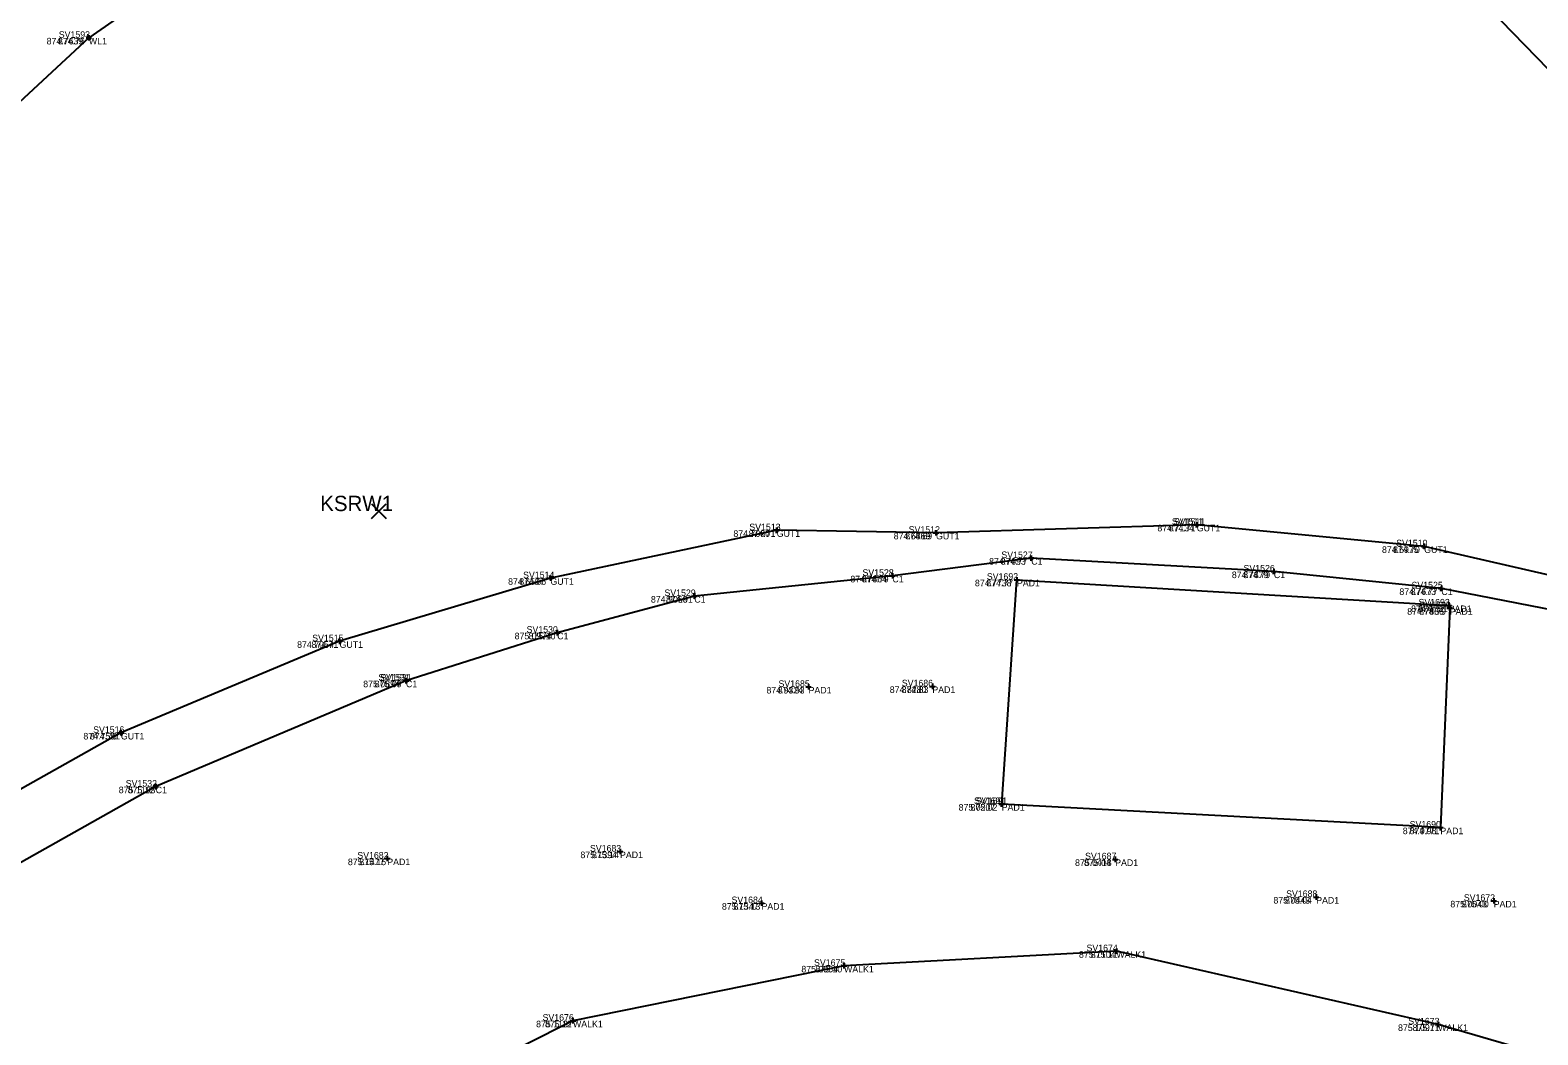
# Model space of a CAD drawing. Extents: x 1475924 to 1484301, y 375879 to 383357.
# Drawn here: x 1480162.05 to 1480175.83, y 379382.77 to 379391.95 of the extents above; entities that cross this region are included whole.
import ezdxf

# ---------------------------------------------------------------- set-up
doc = ezdxf.new("R2010")
doc.units = 0
for name, color, linetype in [('GK_Visualization', 7, 'Continuous'), ('PV_X_Curb', 7, 'Continuous'), ('PV_X_Walk', 7, 'Continuous'), ('RD_X_Concrete_Pad', 7, 'Continuous'), ('SV_X_Random_Point', 7, 'Continuous'), ('SV_X_Shot_Marker', 7, 'Continuous'), ('SV_X_Text_Comment', 7, 'Continuous'), ('SV_X_Text_Elevation', 7, 'Continuous'), ('SV_X_Text_Name', 7, 'Continuous'), ('UT_X_Water', 7, 'Continuous')]:
    doc.layers.add(name, color=color, linetype=linetype)

# ---------------------------------------------------------------- blocks, each defined once
blk = doc.blocks.new('X')
at = {"layer": 'SV_X_Random_Point'}
for p, q in [((-0.067, -0.067), (0.067, 0.067)), ((-0.067, 0.067), (0.067, -0.067))]:
    blk.add_line(p, q, dxfattribs=at)
blk = doc.blocks.new('GTM')
at = {"layer": 'SV_X_Shot_Marker'}
for p, q in [((-0.075, 0), (0.075, 0)), ((0, 0.075), (0, -0.075)), ((0, 0), (0, 0))]:
    blk.add_line(p, q, dxfattribs=at)

msp = doc.modelspace()

# ---------------------------------------------------------------- linework, layer by layer
at = {"layer": 'PV_X_Curb'}
for points in [[(1480233.83, 379339.39), (1480215.875, 379356.288), (1480200.731, 379370.664), (1480190.903, 379379.712), (1480187.53, 379382.642), (1480185.615, 379384.173), (1480181.928, 379385.583), (1480179.411, 379386.173), (1480174.793, 379387.235), (1480172.715, 379387.432), (1480170.332, 379387.359), (1480168.876, 379387.382), (1480166.808, 379386.944), (1480164.881, 379386.368), (1480162.883, 379385.531), (1480159.898, 379383.853), (1480158.052, 379382.754), (1480156.183, 379381.403), (1480155.05, 379380.342)], [(1480233.297, 379339.4), (1480215.447, 379356.074), (1480200.436, 379370.31), (1480191.889, 379378.223), (1480190.185, 379379.842), (1480188.303, 379381.604), (1480185.259, 379383.605), (1480181.861, 379385.001), (1480179.101, 379385.902), (1480178.705, 379386.045), (1480178.118, 379386.223), (1480177.29, 379386.43), (1480176.688, 379386.511), (1480174.95, 379386.851), (1480173.419, 379387.005), (1480171.202, 379387.128), (1480169.933, 379386.966), (1480168.123, 379386.781), (1480166.87, 379386.446), (1480165.488, 379386.008), (1480163.201, 379385.04), (1480160.165, 379383.332), (1480157.23, 379381.331), (1480156.058, 379380.439)]]:
    msp.add_lwpolyline(points, dxfattribs=at)
at = {"layer": 'PV_X_Walk'}
msp.add_lwpolyline([(1480327.959, 379242.083), (1480313.163, 379256.356), (1480297.576, 379270.674), (1480283.951, 379284.205), (1480267.344, 379299.69), (1480258.509, 379307.782), (1480244.036, 379321.372), (1480229.243, 379335.021), (1480213.414, 379349.982), (1480196.806, 379366.202), (1480192.296, 379370.271), (1480186.385, 379375.802), (1480181.8, 379379.27), (1480179.258, 379381.212), (1480177.445, 379382.131), (1480174.921, 379382.868), (1480171.98, 379383.537), (1480169.491, 379383.403), (1480167.014, 379382.902), (1480162.891, 379380.83), (1480161.298, 379379.691), (1480158.915, 379377.808)], dxfattribs=at)
at = {"layer": 'RD_X_Concrete_Pad'}
msp.add_lwpolyline([(1480175.026, 379386.67), (1480174.941, 379384.666), (1480170.932, 379384.881), (1480171.071, 379386.93), (1480175.017, 379386.695)], dxfattribs=at)
at = {"layer": 'SV_X_Shot_Marker'}
for p, q in [((1480162.611, 379391.894), (1480162.569, 379391.866)), ((1480162.604, 379391.859), (1480162.576, 379391.901)), ((1480162.59, 379391.88), (1480162.59, 379391.88)), ((1480168.9, 379387.382), (1480168.851, 379387.382)), ((1480168.875, 379387.357), (1480168.876, 379387.407)), ((1480168.876, 379387.382), (1480168.876, 379387.382)), ((1480170.357, 379387.359), (1480170.307, 379387.358)), ((1480170.332, 379387.334), (1480170.331, 379387.384)), ((1480170.332, 379387.359), (1480170.332, 379387.359)), ((1480172.74, 379387.43), (1480172.69, 379387.434)), ((1480172.713, 379387.407), (1480172.718, 379387.457)), ((1480172.715, 379387.432), (1480172.715, 379387.432)), ((1480174.817, 379387.229), (1480174.768, 379387.241)), ((1480174.787, 379387.211), (1480174.798, 379387.259)), ((1480174.793, 379387.235), (1480174.793, 379387.235)), ((1480171.227, 379387.127), (1480171.177, 379387.13)), ((1480171.201, 379387.103), (1480171.203, 379387.153)), ((1480171.202, 379387.128), (1480171.202, 379387.128)), ((1480166.832, 379386.95), (1480166.783, 379386.939)), ((1480166.813, 379386.92), (1480166.803, 379386.969)), ((1480166.808, 379386.944), (1480166.808, 379386.944)), ((1480169.958, 379386.969), (1480169.908, 379386.963)), ((1480169.936, 379386.941), (1480169.93, 379386.991)), ((1480169.933, 379386.966), (1480169.933, 379386.966)), ((1480171.046, 379386.932), (1480171.096, 379386.928)), ((1480171.069, 379386.905), (1480171.073, 379386.955)), ((1480171.071, 379386.93), (1480171.071, 379386.93)), ((1480173.443, 379387.002), (1480173.394, 379387.007)), ((1480173.416, 379386.98), (1480173.421, 379387.03)), ((1480173.419, 379387.005), (1480173.419, 379387.005)), ((1480168.148, 379386.783), (1480168.098, 379386.778)), ((1480168.126, 379386.756), (1480168.121, 379386.805)), ((1480174.974, 379386.846), (1480174.925, 379386.856)), ((1480174.945, 379386.826), (1480174.955, 379386.876)), ((1480174.95, 379386.851), (1480174.95, 379386.851)), ((1480168.123, 379386.781), (1480168.123, 379386.781)), ((1480174.992, 379386.697), (1480175.042, 379386.694)), ((1480175.051, 379386.669), (1480175.001, 379386.671)), ((1480175.018, 379386.72), (1480175.016, 379386.67)), ((1480175.017, 379386.695), (1480175.017, 379386.695)), ((1480175.027, 379386.695), (1480175.025, 379386.645)), ((1480175.026, 379386.67), (1480175.026, 379386.67)), ((1480164.905, 379386.376), (1480164.857, 379386.361)), ((1480164.889, 379386.344), (1480164.874, 379386.392)), ((1480164.881, 379386.368), (1480164.881, 379386.368)), ((1480166.894, 379386.452), (1480166.846, 379386.439)), ((1480166.877, 379386.421), (1480166.864, 379386.47)), ((1480166.87, 379386.446), (1480166.87, 379386.446)), ((1480165.512, 379386.016), (1480165.464, 379386.001)), ((1480165.495, 379385.984), (1480165.48, 379386.032)), ((1480165.488, 379386.008), (1480165.488, 379386.008)), ((1480169.167, 379385.976), (1480169.167, 379385.926)), ((1480170.273, 379385.956), (1480170.323, 379385.956)), ((1480170.298, 379385.981), (1480170.298, 379385.931)), ((1480170.298, 379385.956), (1480170.298, 379385.956)), ((1480169.142, 379385.951), (1480169.192, 379385.951)), ((1480169.167, 379385.951), (1480169.167, 379385.951)), ((1480162.906, 379385.541), (1480162.86, 379385.522)), ((1480162.893, 379385.508), (1480162.874, 379385.554)), ((1480162.883, 379385.531), (1480162.883, 379385.531)), ((1480163.224, 379385.049), (1480163.178, 379385.03)), ((1480163.211, 379385.016), (1480163.191, 379385.063)), ((1480163.201, 379385.04), (1480163.201, 379385.04)), ((1480170.957, 379384.879), (1480170.907, 379384.882)), ((1480170.931, 379384.856), (1480170.933, 379384.905)), ((1480170.932, 379384.881), (1480170.932, 379384.881)), ((1480174.966, 379384.665), (1480174.916, 379384.667)), ((1480174.942, 379384.691), (1480174.94, 379384.641)), ((1480174.941, 379384.666), (1480174.941, 379384.666)), ((1480167.419, 379384.447), (1480167.469, 379384.447)), ((1480167.444, 379384.472), (1480167.444, 379384.422)), ((1480167.444, 379384.447), (1480167.444, 379384.447)), ((1480165.292, 379384.383), (1480165.342, 379384.383)), ((1480165.317, 379384.408), (1480165.317, 379384.358)), ((1480165.317, 379384.383), (1480165.317, 379384.383)), ((1480171.944, 379384.376), (1480171.994, 379384.376)), ((1480171.969, 379384.401), (1480171.969, 379384.351)), ((1480171.969, 379384.376), (1480171.969, 379384.376)), ((1480173.781, 379384.032), (1480173.831, 379384.032)), ((1480173.806, 379384.057), (1480173.806, 379384.007)), ((1480173.806, 379384.032), (1480173.806, 379384.032)), ((1480168.712, 379383.976), (1480168.762, 379383.976)), ((1480168.737, 379384.001), (1480168.737, 379383.951)), ((1480168.737, 379383.976), (1480168.737, 379383.976)), ((1480175.403, 379383.997), (1480175.453, 379383.997)), ((1480175.428, 379384.022), (1480175.428, 379383.972)), ((1480175.428, 379383.997), (1480175.428, 379383.997)), ((1480172.004, 379383.531), (1480171.956, 379383.543)), ((1480171.974, 379383.513), (1480171.986, 379383.561)), ((1480171.98, 379383.537), (1480171.98, 379383.537)), ((1480169.516, 379383.404), (1480169.466, 379383.401)), ((1480169.492, 379383.378), (1480169.49, 379383.427)), ((1480169.491, 379383.403), (1480169.491, 379383.403)), ((1480167.019, 379382.877), (1480167.009, 379382.926)), ((1480167.039, 379382.907), (1480166.989, 379382.897)), ((1480167.014, 379382.902), (1480167.014, 379382.902)), ((1480174.945, 379382.861), (1480174.897, 379382.875)), ((1480174.914, 379382.844), (1480174.928, 379382.892)), ((1480174.921, 379382.868), (1480174.921, 379382.868))]:
    msp.add_line(p, q, dxfattribs=at)
at = {"layer": 'UT_X_Water'}
for points in [[(1480234.677, 379335.863), (1480225.088, 379345.601), (1480208.322, 379361.342), (1480207.346, 379362.25), (1480199.528, 379369.768), (1480193.21, 379375.651), (1480182.823, 379385.139), (1480177.927, 379389.525), (1480169.423, 379398.321), (1480161.035, 379406.189), (1480144.924, 379421.019), (1480134.739, 379430.559), (1480121.485, 379441.998), (1480113.085, 379450.369), (1480106.418, 379456.915), (1480094.539, 379467.985), (1480089.15, 379472.551), (1480086.751, 379474.713), (1480073.459, 379487.337), (1480068.123, 379493.187), (1480050.678, 379510.207), (1480044.404, 379515.873)], [(1480169.204, 379397.823), (1480165.761, 379394.087), (1480162.59, 379391.88), (1480159.156, 379388.706), (1480148.911, 379378.819), (1480120.344, 379350.087), (1480106.297, 379335.736), (1480080.736, 379308.289), (1480073.091, 379299.637), (1480056.748, 379281.628), (1480051.266, 379275.974)]]:
    msp.add_lwpolyline(points, dxfattribs=at)

# ---------------------------------------------------------------- block references
at = {"layer": 'GK_Visualization'}
msp.add_blockref('X', (1480165.24, 379387.557), dxfattribs=at)
at = {"layer": 'SV_X_Shot_Marker', "xscale": 0.3333333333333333, "yscale": 0.3333333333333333}
for p in [(1480162.59, 379391.88), (1480168.876, 379387.382), (1480170.332, 379387.359), (1480172.715, 379387.432), (1480174.793, 379387.235), (1480171.202, 379387.128), (1480166.808, 379386.944), (1480169.933, 379386.966), (1480171.071, 379386.93), (1480173.419, 379387.005), (1480168.123, 379386.781), (1480174.95, 379386.851), (1480175.017, 379386.695), (1480175.026, 379386.67), (1480164.881, 379386.368), (1480166.87, 379386.446), (1480165.488, 379386.008), (1480169.167, 379385.951), (1480170.298, 379385.956), (1480162.883, 379385.531), (1480163.201, 379385.04), (1480170.932, 379384.881), (1480174.941, 379384.666), (1480167.444, 379384.447), (1480165.317, 379384.383), (1480171.969, 379384.376), (1480173.806, 379384.032), (1480168.737, 379383.976), (1480175.428, 379383.997), (1480171.98, 379383.537), (1480169.491, 379383.403), (1480167.014, 379382.902), (1480174.921, 379382.868)]:
    msp.add_blockref('GTM', p, dxfattribs=at)

# ---------------------------------------------------------------- texts
at = {"layer": 'GK_Visualization'}
msp.add_text('KSRW1', height=0.14, dxfattribs=at).set_placement((1480164.704, 379387.557))
at = {"layer": 'SV_X_Text_Comment'}
for s, p in [('WL1', (1480162.59, 379391.82)), ('GUT1', (1480168.876, 379387.322)), ('GUT1', (1480170.332, 379387.299)), ('GUT1', (1480172.715, 379387.372)), ('GUT1', (1480174.793, 379387.175)), ('C1', (1480171.202, 379387.068)), ('GUT1', (1480166.808, 379386.884)), ('C1', (1480169.933, 379386.906)), ('PAD1', (1480171.071, 379386.87)), ('C1', (1480173.419, 379386.945)), ('C1', (1480168.123, 379386.721)), ('C1', (1480174.95, 379386.791)), ('PAD1', (1480175.017, 379386.635)), ('PAD1', (1480175.026, 379386.61)), ('GUT1', (1480164.881, 379386.308)), ('C1', (1480166.87, 379386.386)), ('C1', (1480165.488, 379385.948)), ('PAD1', (1480170.298, 379385.896)), ('PAD1', (1480169.167, 379385.891)), ('GUT1', (1480162.883, 379385.471)), ('C1', (1480163.201, 379384.98)), ('PAD1', (1480170.932, 379384.821)), ('PAD1', (1480174.941, 379384.606)), ('PAD1', (1480167.444, 379384.387)), ('PAD1', (1480165.317, 379384.323)), ('PAD1', (1480171.969, 379384.316)), ('PAD1', (1480173.806, 379383.972)), ('PAD1', (1480168.737, 379383.916)), ('PAD1', (1480175.428, 379383.937)), ('WALK1', (1480171.98, 379383.477)), ('WALK1', (1480169.491, 379383.343)), ('WALK1', (1480167.014, 379382.842)), ('WALK1', (1480174.921, 379382.808))]:
    msp.add_text(s, height=0.06, dxfattribs=at).set_placement(p)
at = {"layer": 'SV_X_Text_Elevation'}
for s, p in [('874.7639', (1480162.204, 379391.82)), ('874.76', (1480162.307, 379391.82)), ('874.76', (1480162.307, 379391.82)), ('874.7090', (1480168.48, 379387.322)), ('874.71', (1480168.619, 379387.322)), ('874.71', (1480168.619, 379387.322)), ('874.6869', (1480169.945, 379387.299)), ('874.69', (1480170.05, 379387.299)), ('874.69', (1480170.05, 379387.299)), ('874.7134', (1480172.355, 379387.372)), ('874.71', (1480172.458, 379387.372)), ('874.71', (1480172.458, 379387.372)), ('874.6975', (1480174.407, 379387.175)), ('874.70', (1480174.508, 379387.175)), ('874.70', (1480174.508, 379387.175)), ('874.7693', (1480170.817, 379387.068)), ('874.77', (1480170.922, 379387.068)), ('874.77', (1480170.922, 379387.068)), ('874.6597', (1480166.421, 379386.884)), ('874.66', (1480166.523, 379386.884)), ('874.66', (1480166.523, 379386.884)), ('874.7864', (1480169.549, 379386.906)), ('874.79', (1480169.653, 379386.906)), ('874.79', (1480169.653, 379386.906)), ('874.7738', (1480170.687, 379386.87)), ('874.77', (1480170.791, 379386.87)), ('874.77', (1480170.791, 379386.87)), ('874.7879', (1480173.035, 379386.945)), ('874.79', (1480173.139, 379386.945)), ('874.79', (1480173.139, 379386.945)), ('874.9060', (1480167.726, 379386.721)), ('874.91', (1480167.864, 379386.721)), ('874.91', (1480167.864, 379386.721)), ('874.7673', (1480174.566, 379386.791)), ('874.77', (1480174.67, 379386.791)), ('874.77', (1480174.67, 379386.791)), ('874.7866', (1480174.638, 379386.61)), ('874.7731', (1480174.673, 379386.635)), ('874.77', (1480174.737, 379386.635)), ('874.77', (1480174.737, 379386.635)), ('874.79', (1480174.746, 379386.61)), ('874.79', (1480174.746, 379386.61)), ('874.7054', (1480164.493, 379386.308)), ('874.71', (1480164.624, 379386.308)), ('874.71', (1480164.624, 379386.308)), ('875.0974', (1480166.481, 379386.386)), ('875.10', (1480166.608, 379386.386)), ('875.10', (1480166.608, 379386.386)), ('875.0894', (1480165.097, 379385.948)), ('875.09', (1480165.202, 379385.948)), ('875.09', (1480165.202, 379385.948)), ('874.8280', (1480169.909, 379385.896)), ('874.83', (1480170.017, 379385.896)), ('874.83', (1480170.017, 379385.896)), ('874.9324', (1480168.782, 379385.891)), ('874.93', (1480168.885, 379385.891)), ('874.93', (1480168.885, 379385.891)), ('874.7581', (1480162.54, 379385.471)), ('874.76', (1480162.6, 379385.471)), ('874.76', (1480162.6, 379385.471)), ('875.1193', (1480162.863, 379384.98)), ('875.12', (1480162.945, 379384.98)), ('875.12', (1480162.945, 379384.98)), ('875.0207', (1480170.538, 379384.821)), ('875.02', (1480170.647, 379384.821)), ('875.02', (1480170.647, 379384.821)), ('874.9771', (1480174.597, 379384.606)), ('874.98', (1480174.659, 379384.606)), ('874.98', (1480174.659, 379384.606)), ('875.1394', (1480167.082, 379384.387)), ('875.14', (1480167.188, 379384.387)), ('875.14', (1480167.188, 379384.387)), ('875.1477', (1480164.957, 379384.323)), ('875.15', (1480165.061, 379384.323)), ('875.15', (1480165.061, 379384.323)), ('875.0418', (1480171.602, 379384.316)), ('875.04', (1480171.684, 379384.316)), ('875.04', (1480171.684, 379384.316)), ('875.0443', (1480173.415, 379383.972)), ('875.04', (1480173.521, 379383.972)), ('875.04', (1480173.521, 379383.972)), ('875.1347', (1480168.375, 379383.916)), ('875.13', (1480168.481, 379383.916)), ('875.13', (1480168.481, 379383.916)), ('875.0043', (1480175.032, 379383.937)), ('875.00', (1480175.137, 379383.937)), ('875.00', (1480175.137, 379383.937)), ('875.1104', (1480171.638, 379383.477)), ('875.11', (1480171.746, 379383.477)), ('875.11', (1480171.746, 379383.477)), ('875.0954', (1480169.101, 379383.343)), ('875.10', (1480169.229, 379383.343)), ('875.10', (1480169.229, 379383.343)), ('875.1187', (1480166.677, 379382.842)), ('875.12', (1480166.758, 379382.842)), ('875.12', (1480166.758, 379382.842)), ('875.1097', (1480174.554, 379382.808)), ('875.11', (1480174.687, 379382.808)), ('875.11', (1480174.687, 379382.808))]:
    msp.add_text(s, height=0.06, dxfattribs=at).set_placement(p)
at = {"layer": 'SV_X_Text_Name'}
for s, p in [('SV1593', (1480162.315, 379391.88)), ('SV1593', (1480162.315, 379391.88)), ('SV1593', (1480162.315, 379391.88)), ('SV1511', (1480172.487, 379387.432)), ('SV1511', (1480172.487, 379387.432)), ('SV1511', (1480172.505, 379387.432)), ('SV1513', (1480168.625, 379387.382)), ('SV1513', (1480168.626, 379387.382)), ('SV1513', (1480168.626, 379387.382)), ('SV1512', (1480170.082, 379387.359)), ('SV1512', (1480170.082, 379387.359)), ('SV1512', (1480170.082, 379387.359)), ('SV1510', (1480174.537, 379387.235)), ('SV1510', (1480174.537, 379387.235)), ('SV1510', (1480174.537, 379387.235)), ('SV1527', (1480170.929, 379387.128)), ('SV1527', (1480170.929, 379387.128)), ('SV1527', (1480170.929, 379387.128)), ('SV1526', (1480173.142, 379387.005)), ('SV1526', (1480173.142, 379387.005)), ('SV1526', (1480173.142, 379387.005)), ('SV1514', (1480166.558, 379386.944)), ('SV1514', (1480166.558, 379386.944)), ('SV1514', (1480166.558, 379386.944)), ('SV1528', (1480169.659, 379386.966)), ('SV1528', (1480169.66, 379386.966)), ('SV1528', (1480169.66, 379386.966)), ('SV1692', (1480170.796, 379386.93)), ('SV1692', (1480170.796, 379386.93)), ('SV1692', (1480170.796, 379386.93)), ('SV1529', (1480167.85, 379386.781)), ('SV1529', (1480167.85, 379386.781)), ('SV1529', (1480167.85, 379386.781)), ('SV1525', (1480174.677, 379386.851)), ('SV1525', (1480174.677, 379386.851)), ('SV1525', (1480174.677, 379386.851)), ('SV1693', (1480174.741, 379386.695)), ('SV1693', (1480174.741, 379386.695)), ('SV1693', (1480174.741, 379386.695)), ('SV1689', (1480174.751, 379386.67)), ('SV1689', (1480174.751, 379386.67)), ('SV1689', (1480174.751, 379386.67)), ('SV1530', (1480166.59, 379386.446)), ('SV1530', (1480166.59, 379386.446)), ('SV1530', (1480166.59, 379386.446)), ('SV1515', (1480164.631, 379386.368)), ('SV1515', (1480164.631, 379386.368)), ('SV1515', (1480164.631, 379386.368)), ('SV1531', (1480165.236, 379386.008)), ('SV1531', (1480165.236, 379386.008)), ('SV1531', (1480165.253, 379386.008)), ('SV1685', (1480168.892, 379385.951)), ('SV1685', (1480168.892, 379385.951)), ('SV1685', (1480168.892, 379385.951)), ('SV1686', (1480170.019, 379385.956)), ('SV1686', (1480170.019, 379385.956)), ('SV1686', (1480170.019, 379385.956)), ('SV1516', (1480162.629, 379385.531)), ('SV1516', (1480162.629, 379385.531)), ('SV1516', (1480162.629, 379385.531)), ('SV1532', (1480162.927, 379385.04)), ('SV1532', (1480162.927, 379385.04)), ('SV1532', (1480162.927, 379385.04)), ('SV1691', (1480170.679, 379384.881)), ('SV1691', (1480170.679, 379384.881)), ('SV1691', (1480170.696, 379384.881)), ('SV1690', (1480174.66, 379384.666)), ('SV1690', (1480174.66, 379384.666)), ('SV1690', (1480174.66, 379384.666)), ('SV1682', (1480165.043, 379384.383)), ('SV1682', (1480165.043, 379384.383)), ('SV1682', (1480165.043, 379384.383)), ('SV1683', (1480167.169, 379384.447)), ('SV1683', (1480167.169, 379384.447)), ('SV1683', (1480167.169, 379384.447)), ('SV1687', (1480171.694, 379384.376)), ('SV1687', (1480171.694, 379384.376)), ('SV1687', (1480171.694, 379384.376)), ('SV1684', (1480168.463, 379383.976)), ('SV1684', (1480168.463, 379383.976)), ('SV1684', (1480168.463, 379383.976)), ('SV1688', (1480173.531, 379384.032)), ('SV1688', (1480173.531, 379384.032)), ('SV1688', (1480173.531, 379384.032)), ('SV1672', (1480175.155, 379383.997)), ('SV1672', (1480175.155, 379383.997)), ('SV1672', (1480175.155, 379383.997)), ('SV1674', (1480171.707, 379383.537)), ('SV1674', (1480171.707, 379383.537)), ('SV1674', (1480171.707, 379383.537)), ('SV1675', (1480169.217, 379383.403)), ('SV1675', (1480169.217, 379383.403)), ('SV1675', (1480169.217, 379383.403)), ('SV1676', (1480166.736, 379382.902)), ('SV1676', (1480166.736, 379382.902)), ('SV1676', (1480166.736, 379382.902)), ('SV1673', (1480174.647, 379382.868)), ('SV1673', (1480174.647, 379382.868)), ('SV1673', (1480174.647, 379382.868))]:
    msp.add_text(s, height=0.06, dxfattribs=at).set_placement(p)

doc.saveas('drawing.dxf')
